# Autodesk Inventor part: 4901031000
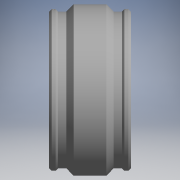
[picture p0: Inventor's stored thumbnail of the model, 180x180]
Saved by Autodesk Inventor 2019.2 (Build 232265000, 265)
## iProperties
Created: 2017-06
Part Number: 4901031000
Material: Generic
Description: PLASSON COUPLER 1000
Document SubType Name: Modeling
Designer: KIM
Mass: 96874 g
Surface Area: 34549.7 cm^2
Volume: 96874 cm^3
Density: 1 g/cm^3
Appearance: Default
Author: KIM
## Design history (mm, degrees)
derived "490103.ipt"
feature "Solid1::490103.ipt"
tag "TaggingFeature1"
body "Solid1"
other parameters: "d15" = 285, "d16" = 285, "d22" = 1126, "d23" = 1194, "d24" = 1092.22, "d25" = 135 deg, "d26" = 228, "d27" = 135 deg, "d29" = 563, "d35" = 15, "d39" = 0, "d40" = 4, "d41" = 14, "d42" = 0, "d43" = 135 deg, "d44" = 62.7, "d46" = 6, "d47" = 0, "L_1" = 285, "D_" = 1194, "A_" = 563, "d_2" = 12
